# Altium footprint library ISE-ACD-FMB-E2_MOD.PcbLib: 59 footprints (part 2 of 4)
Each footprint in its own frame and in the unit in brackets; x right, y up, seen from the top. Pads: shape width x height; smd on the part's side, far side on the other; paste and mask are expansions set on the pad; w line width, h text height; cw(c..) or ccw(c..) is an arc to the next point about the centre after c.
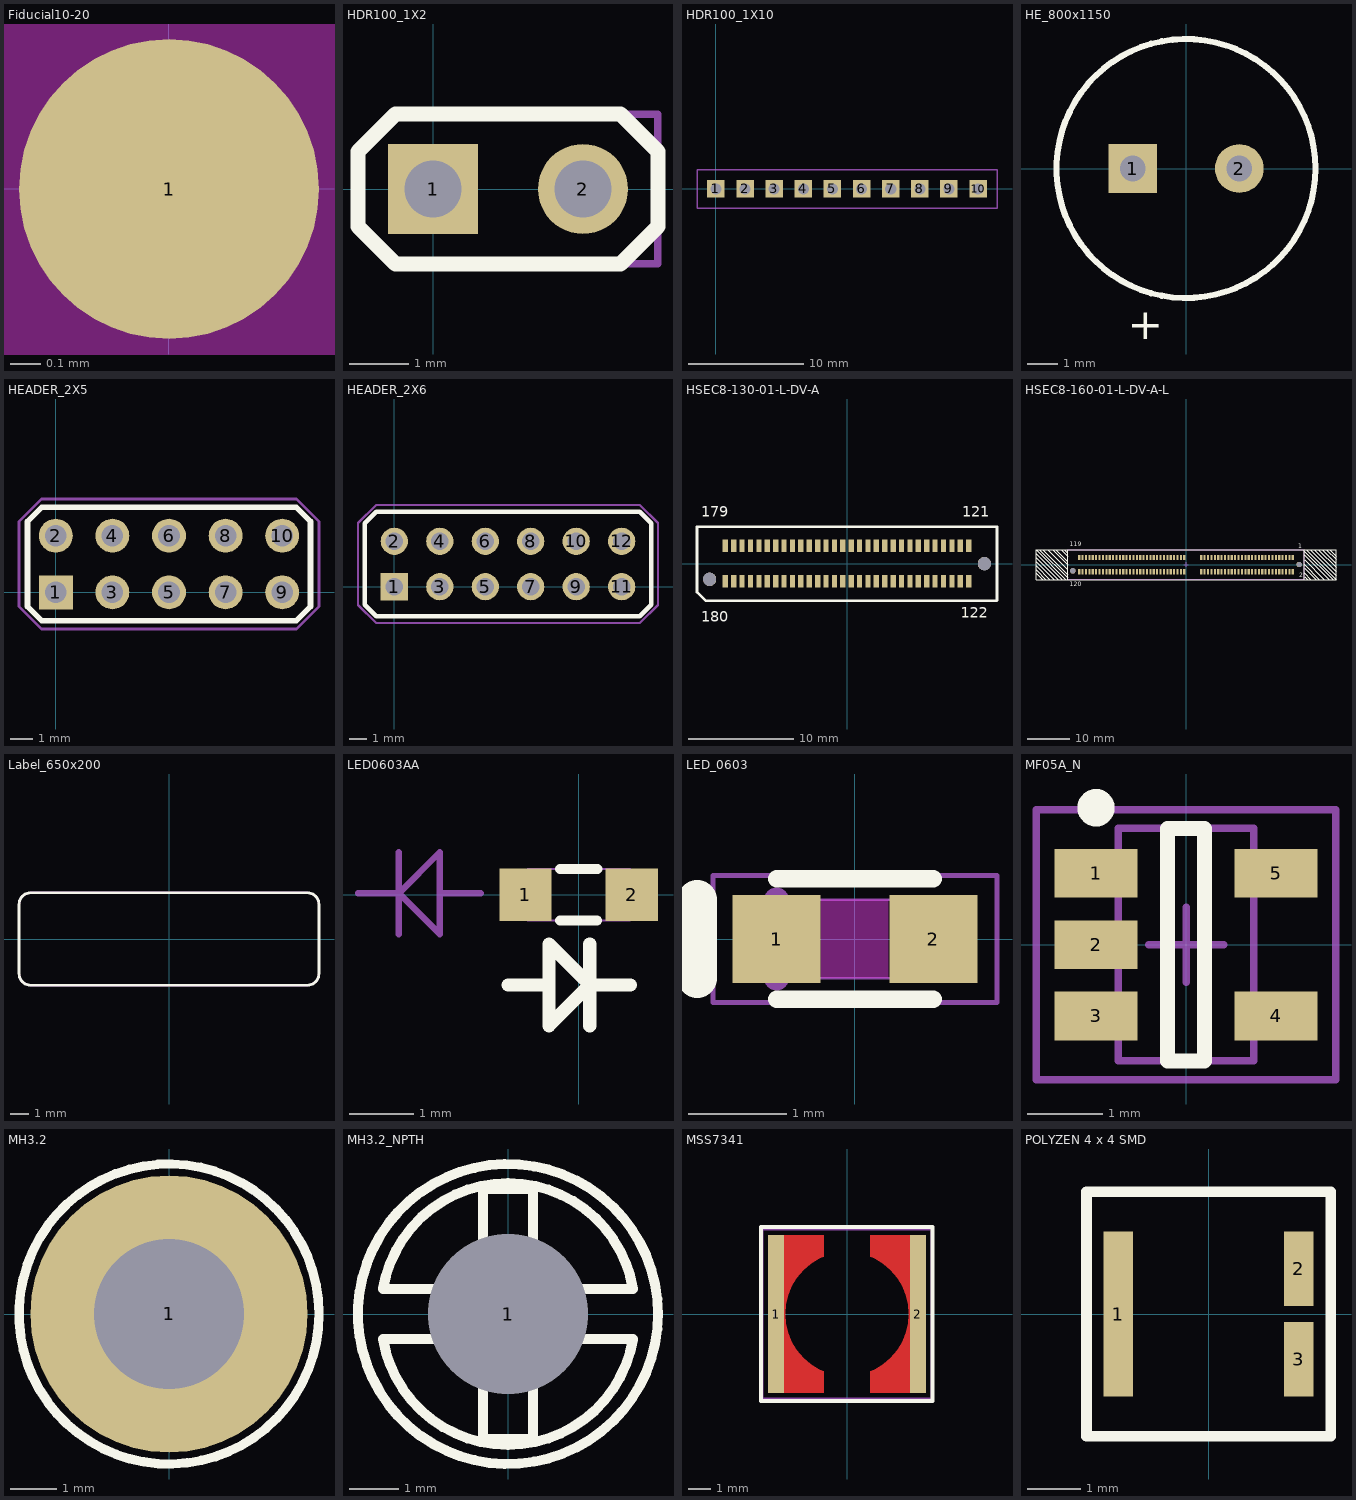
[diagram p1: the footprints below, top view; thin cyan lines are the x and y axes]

## Fiducial10-20 [mm]
pads (1):
  round 1 smd mask+0.5: 1(0,0)
Top Layer keep-out:
  circle w1.178: c0,0 r0.5

## HDR100_1X2 [mil]
pads (2):
  rect 60x60 hole 38: 1(0,0)
  round 60 hole 38: 2(100,0)
Top Overlay:
  lines w10: -50,-25 -50,25 -25,50 125,50 150,25 150,-25 125,-50 -25,-50 -50,-25
Mechanical 5:
  lines w5: -50,-25 -25,-50 150,-50 150,50 -25,50 -50,25 -50,-25
  text ".Designator" at 70,-46 h36

## HDR100_1X10 [mil]
pads (10):
  rect 60x60 hole 38: 1(0,0) 2(100,0) 3(200,0) 4(300,0) 5(400,0) 6(500,0) 7(600,0) 8(700,0) 9(800,0) 10(900,0)
Mechanical 5:
  lines w5: -65.1,-66 964.9,-66 964.9,65 -65.1,65 -65.1,-66
  text "*" at -47,16 h40
  text ".Designator" at 410,74 h36

## HE_800x1150 [mm] "NICHICON"
height 13
pads (2):
  rect 1.6x1.6 hole 0.838: 1(-1.75,0)
  round 1.6 hole 0.838: 2(1.75,0)
Top Overlay:
  circle w0.2: c0,0 r4.25
  text "+" at -1.905,-5.595 h1.02
Mechanical 5:
  circle w0.1: c0,0 r4.25
  text "+" at -5.2,-0.5 h1.02
  text ".Designator" at -0.457,1.295 h0.91
3D body: height 11.51, standoff -4, extent -4.217,-4.243 4.244,4.243

## HEADER_2X5 [mil]
pads (10):
  rect 60x60 hole 38: 1(0,0)
  round 60 hole 38: 2(0,100) 3(100,0) 4(100,100) 5(200,0) 6(200,100) 7(300,0) 8(300,100) 9(400,0) 10(400,100)
Top Overlay:
  lines w10: -50,-25 -25,-50 425,-50 450,-25 450,125 425,150 -25,150 -50,125 -50,-25
Mechanical 5:
  lines w5: -65,-25 -25,-65 425,-65 465,-25 465,125 425,165 -25,165 -65,125 -65,-25
  text "*" at -32,-47 h40
  text ".Designator" at 247,69 h36

## HEADER_2X6 [mil]
pads (12):
  rect 60x60 hole 38: 1(0,0)
  round 60 hole 38: 2(0,100) 3(100,0) 4(100,100) 5(200,0) 6(200,100) 7(300,0) 8(300,100) 9(400,0) 10(400,100) 11(500,0) 12(500,100)
Top Overlay:
  lines w10: -65,-40 -40,-65 540,-65 565,-40 565,140 540,165 -40,165 -65,140 -65,-40
Mechanical 5:
  lines w5: -80,-40 -40,-80 540,-80 580,-40 580,140 540,180 -40,180 -80,140 -80,-40
  text "*" at -46,-58 h40
  text ".Designator" at 268,4 h36

## HSEC8-130-01-L-DV-A [mm]
pads (62):
  rect 0.5x1.2 smd: 121(11.6,1.7) 122(11.6,-1.7) 123(10.8,1.7) 124(10.8,-1.7) 125(10,1.7) 126(10,-1.7) 127(9.2,1.7) 128(9.2,-1.7) 129(8.4,1.7) 130(8.4,-1.7) 131(7.6,1.7) 132(7.6,-1.7) 133(6.8,1.7) 134(6.8,-1.7) 135(6,1.7) 136(6,-1.7) 137(5.2,1.7) 138(5.2,-1.7) 139(4.4,1.7) 140(4.4,-1.7) 141(3.6,1.7) 142(3.6,-1.7) 143(2.8,1.7) 144(2.8,-1.7) 145(2,1.7) 146(2,-1.7) 147(1.2,1.7) 148(1.2,-1.7) 149(0.4,1.7) 150(0.4,-1.7) 151(-0.4,1.7) 152(-0.4,-1.7) 153(-1.2,1.7) 154(-1.2,-1.7) 155(-2,1.7) 156(-2,-1.7) 157(-2.8,1.7) 158(-2.8,-1.7) 159(-3.6,1.7) 160(-3.6,-1.7) 161(-4.4,1.7) 162(-4.4,-1.7) 163(-5.2,1.7) 164(-5.2,-1.7) 165(-6,1.7) 166(-6,-1.7) 167(-6.8,1.7) 168(-6.8,-1.7) 169(-7.6,1.7) 170(-7.6,-1.7) 171(-8.4,1.7) 172(-8.4,-1.7) 173(-9.2,1.7) 174(-9.2,-1.7) 175(-10,1.7) 176(-10,-1.7) 177(-10.8,1.7) 178(-10.8,-1.7) 179(-11.6,1.7) 180(-11.6,-1.7)
  round 1.27 hole 1.27 unplated mask+0.127: 181(13.1,0) 182(-13.1,-1.5)
Top Overlay:
  lines w0.254: 14.246,-3.554 -13.464,-3.554 -14.3,-2.718 -14.3,1.75 -14.3,3.5 14.3,3.5 14.3,-3.5
  text "180" at -13.898,-5.563 h1.02
  text "179" at -13.898,4.47 h1.02
  text "121" at 10.994,4.47 h1.02
  text "122" at 10.867,-5.182 h1.02
Mechanical 13:
  lines w0.1: -14.3,-2.7 -14.3,3.5 14.3,3.5 14.3,-3.5 -13.5,-3.5 -14.3,-2.7

## HSEC8-160-01-L-DV-A-L [mm] "CONN HIGH SPD CARD EDGE 120 POS"
height 12.4
pads (122):
  rect 0.5x1.2 smd: 1(25.2,1.7) 2(25.2,-1.7) 3(24.4,1.7) 4(24.4,-1.7) 5(23.6,1.7) 6(23.6,-1.7) 7(22.8,1.7) 8(22.8,-1.7) 9(22,1.7) 10(22,-1.7) 11(21.2,1.7) 12(21.2,-1.7) 13(20.4,1.7) 14(20.4,-1.7) 15(19.6,1.7) 16(19.6,-1.7) 17(18.8,1.7) 18(18.8,-1.7) 19(18,1.7) 20(18,-1.7) 21(17.2,1.7) 22(17.2,-1.7) 23(16.4,1.7) 24(16.4,-1.7) 25(15.6,1.7) 26(15.6,-1.7) 27(14.8,1.7) 28(14.8,-1.7) 29(14,1.7) 30(14,-1.7) 31(13.2,1.7) 32(13.2,-1.7) 33(12.4,1.7) 34(12.4,-1.7) 35(11.6,1.7) 36(11.6,-1.7) 37(10.8,1.7) 38(10.8,-1.7) 39(10,1.7) 40(10,-1.7) 41(9.2,1.7) 42(9.2,-1.7) 43(8.4,1.7) 44(8.4,-1.7) 45(7.6,1.7) 46(7.6,-1.7) 47(6.8,1.7) 48(6.8,-1.7) 49(6,1.7) 50(6,-1.7) 51(5.2,1.7) 52(5.2,-1.7) 53(4.4,1.7) 54(4.4,-1.7) 55(3.6,1.7) 56(3.6,-1.7) 57(-0.4,1.7) 58(-0.4,-1.7) 59(-1.2,1.7) 60(-1.2,-1.7) 61(-2,1.7) 62(-2,-1.7) 63(-2.8,1.7) 64(-2.8,-1.7) 65(-3.6,1.7) 66(-3.6,-1.7) 67(-4.4,1.7) 68(-4.4,-1.7) 69(-5.2,1.7) 70(-5.2,-1.7) 71(-6,1.7) 72(-6,-1.7) 73(-6.8,1.7) 74(-6.8,-1.7) 75(-7.6,1.7) 76(-7.6,-1.7) 77(-8.4,1.7) 78(-8.4,-1.7) 79(-9.2,1.7) 80(-9.2,-1.7) 81(-10,1.7) 82(-10,-1.7) 83(-10.8,1.7) 84(-10.8,-1.7) 85(-11.6,1.7) 86(-11.6,-1.7) 87(-12.4,1.7) 88(-12.4,-1.7) 89(-13.2,1.7) 90(-13.2,-1.7) 91(-14,1.7) 92(-14,-1.7) 93(-14.8,1.7) 94(-14.8,-1.7) 95(-15.6,1.7) 96(-15.6,-1.7) 97(-16.4,1.7) 98(-16.4,-1.7) 99(-17.2,1.7) 100(-17.2,-1.7) 101(-18,1.7) 102(-18,-1.7) 103(-18.8,1.7) 104(-18.8,-1.7) 105(-19.6,1.7) 106(-19.6,-1.7) 107(-20.4,1.7) 108(-20.4,-1.7) 109(-21.2,1.7) 110(-21.2,-1.7) 111(-22,1.7) 112(-22,-1.7) 113(-22.8,1.7) 114(-22.8,-1.7) 115(-23.6,1.7) 116(-23.6,-1.7) 117(-24.4,1.7) 118(-24.4,-1.7) 119(-25.2,1.7) 120(-25.2,-1.7)
  round 1.27 hole 1.27 unplated mask+0.127: 121(-26.7,-1.5) 122(26.7,0)
Top Overlay:
  lines w0.2: -35.4,-2.032 -33.909,-3.523 ; -35.4,-1.27 -33.114,-3.556 ; -35.4,0.635 -31.242,-3.523 ; -35.4,1.651 -30.226,-3.523 ; -35.4,2.54 -29.337,-3.523 ; -35.353,-0.334 -32.131,-3.556 ; -34.58,3.465 -27.94,-3.175 ; -33.782,3.5 -27.9,-2.382 ; -32.639,3.5 -27.996,-1.143 ; -31.496,3.5 -27.9,-0.096 ; -30.734,3.5 -27.996,0.762 ; -29.464,3.5 -27.9,1.936 ; -28.702,3.5 -27.996,2.794 ; -28.344,-3.556 -35.4,3.5 ; 27.9,-1.992 29.464,-3.556 ; 27.9,0.04 31.496,-3.556 ; 27.9,2.326 33.782,-3.556 ; 27.94,3.119 34.58,-3.52 ; 27.996,-2.85 28.702,-3.556 ; 27.996,-0.818 30.734,-3.556 ; 27.996,1.087 32.639,-3.556 ; 28.344,3.5 35.4,-3.556 ; 29.337,3.467 35.4,-2.596 ; 30.226,3.467 35.4,-1.707 ; 31.242,3.467 35.4,-0.691 ; 32.131,3.5 35.353,0.278 ; 33.114,3.5 35.4,1.214 ; 33.909,3.467 35.4,1.976 ; -35.4,3.5 -27.9,3.5 ; -35.4,3.5 -35.4,-3.556 -27.9,-3.556 ; -27.9,-3.556 -27.9,3.5 ; -27.9,-3.556 27.9,-3.556 ; -27.9,3.5 27.9,3.5 ; 27.9,-3.556 27.9,3.5 ; 27.9,-3.556 35.4,-3.556 ; 27.9,-3.556 27.9,3.5 ; 27.9,3.5 35.4,3.5 35.4,-3.556
  text "2" at 26.67,-3.048 h1.02
  text "1" at 26.543,3.81 h1.02
  text "119" at -27.432,4.318 h1.02
  text "120" at -27.432,-5.08 h1.02
Mechanical 13:
  lines w0.1: 27.9,-3.556 27.9,3.444 ; -27.9,-3.5 27.9,-3.5 27.9,3.5 -27.9,3.5 -27.9,-3.5
Mechanical 15:
  lines w0.1: -0.5,0 0.5,0 ; 0,-0.5 0,0.5

## Label_650x200 [mm] "Thermal Transfer Label"
height 0.025
Top Overlay:
  lines w0.152: -8.255,-1.905 ccw(c-7.62,-1.905) -7.62,-2.54 7.62,-2.54 ccw(c7.62,-1.905) 8.255,-1.905 8.255,1.905 ccw(c7.62,1.905) 7.62,2.54 -7.62,2.54 ccw(c-7.62,1.905) -8.255,1.905 -8.255,-1.905
Mechanical 5:
  lines w0.127: -8.255,-1.905 ccw(c-7.62,-1.905) -7.62,-2.54 7.62,-2.54 ccw(c7.62,-1.905) 8.255,-1.905 8.255,1.905 ccw(c7.62,1.905) 7.62,2.54 -7.62,2.54 ccw(c-7.62,1.905) -8.255,1.905 -8.255,-1.905
  text ".Designator" at -1.524,-0.508 h0.91
3D body: height 0.03, standoff 0, extent -8.268,-2.553 8.268,2.553

## LED0603AA [mil]
height 35.43
pads (2):
  rect 32x32 smd: 1(-32.48,0) 2(32.48,0)
Top Overlay:
  lines w6: -11.42,-15.75 11.42,-15.75 ; -11.42,15.75 11.42,15.75
  lines w8: -43.21,-55.04 -18.21,-55.04 ; 6.79,-80.04 6.79,-30.04 ; 31.79,-55.04 6.79,-55.04 ; 6.79,-55.04 -18.21,-30.04 -18.21,-80.04 6.79,-55.04
Mechanical 15:
  lines w1: -31.5,-15.75 -31.5,15.75 31.5,15.75 31.5,-15.75 -31.5,-15.75
  lines w3.94: -134.79,0.96 -109.79,0.96 ; -109.79,-24.04 -109.79,25.96 ; -84.79,0.96 -59.79,0.96 ; -109.79,0.96 -84.79,-24.04 -84.79,25.96 -109.79,0.96

## LED_0603 [mm] "LED, HIGHBRIGHT, BLUE, SMT0603"
height 0.8
pads (2):
  rect 0.9x0.9 smd paste+0: 1(-0.8,0) 2(0.8,0)
Top Layer keep-out:
  rectangle: -0.35,-0.4 0.344,0.402
Top Overlay:
  lines w0.178: -0.8,-0.616 0.8,-0.616 ; -0.8,0.616 0.8,0.616
  lines w0.405: -1.613,-0.4 -1.613,0.4
  text ".Designator" at -1.524,1 h1.02
Mechanical 5:
  lines w0.025: -0.8,-0.4 0.8,-0.4 0.8,0.4 -0.8,0.4
  lines w0.254: -0.8,-0.4 -0.8,0.4
  text ".Designator" at -1.524,-0.508 h1.02
Mechanical 15:
  lines w0.05: -1.45,-0.65 1.45,-0.65 1.45,0.65 -1.45,0.65 -1.45,-0.65
3D body: height 0.8, standoff 0, extent -0.8,-0.4 0.8,0.4

## MF05A_N [mm] "SOT23, 5-Leads, Body 2.9x1.6mm, Pitch 0.95mm, Lead Span 2.8mm, IPC Medium Density"
height 1.19
pads (5):
  rect 1.1x0.65 smd: 1(-1.2,0.95) 2(-1.2,0) 3(-1.2,-0.95) 4(1.2,-0.95) 5(1.2,0.95)
Top Overlay:
  circle w0.25: c-1.2,1.825 r0.125
  lines w0.2: -0.25,-1.55 -0.25,1.55 0.25,1.55 0.25,-1.55 -0.25,-1.55
Mechanical 5:
  text ".Designator" at 0.457,-0.737 h0.91
Mechanical 13:
  lines w0.1: -0.9,-1.55 0.9,-1.55 0.9,1.55 -0.9,1.55 -0.9,-1.55
Mechanical 15:
  lines w0.1: -0.5,0 0.5,0 ; 0,-0.5 0,0.5 ; -2,-1.8 2,-1.8 2,1.8 -2,1.8 -2,-1.8
3D body: height 1.19, standoff 0, extent -0.9,-1.55 0.9,1.55

## MH3.2 [mm]
height 2.032
pads (1):
  round 6 / inner round 3.607 / far side round 6 hole 3.251: 1(0,0)
Top Overlay:
  lines w0.203: 3.25,0 cw(c0,0) 3.25,0.014

## MH3.2_NPTH [mil]
pads (1):
  round 20 / inner round 142 / far side round 20 hole 128 unplated mask+65: 1(0,0)
Top Overlay:
  circle w8: c0,0 r120
  lines w8: -100,-20 -20,-20 -20,-100 20,-100 20,-20 100,-20 ; -100.02,-19.91 ccw(c0,-3.35) 99.99,-20.08 ; -100,20 -20,20 -20,100 20,100 20,20 100,20 ; -99.99,20.09 cw(c0,3.36) 100.02,19.92

## MSS7341 [mm] "Coilcraft recommended land pattern Document 383-2 1/3/11"
height 4.1
pads (2):
  rect 0.725x7.112 smd: 1(-3.187,0) 2(3.187,0)
Top Layer:
  region: 1.05,-3.55 1.05,-2.57 1.05,-2.569 1.264,-2.48 1.636,-2.252 1.968,-1.968 2.252,-1.636 2.48,-1.264 2.647,-0.86 2.749,-0.435 2.784,0 2.749,0.435 2.647,0.86 2.48,1.264 2.252,1.636 1.968,1.968 1.636,2.252 1.264,2.48 1.057,2.566 1.05,2.566 1.05,3.55 3.55,3.55 3.55,-3.55
  region: -1.05,-3.55 -1.05,-2.57 -1.05,-2.569 -1.264,-2.48 -1.636,-2.252 -1.968,-1.968 -2.252,-1.636 -2.48,-1.264 -2.647,-0.86 -2.749,-0.435 -2.784,0 -2.749,0.435 -2.647,0.86 -2.48,1.264 -2.252,1.636 -1.968,1.968 -1.636,2.252 -1.264,2.48 -1.057,2.566 -1.05,2.566 -1.05,3.55 -3.55,3.55 -3.55,-3.55
Top Overlay:
  lines w0.178: -3.861,-1.397 -3.861,1.372 -3.861,3.912 -3.556,3.912 2.286,3.912 ; -3.861,-1.372 -3.861,-3.912 -2.921,-3.912 ; -2.896,-3.912 2.946,-3.912 3.835,-3.912 3.835,-1.143 ; 2.311,3.912 3.835,3.912 3.835,-1.168
Top Paste:
  region: -1.05,-3.55 -1.05,-2.57 -1.05,-2.569 -1.264,-2.48 -1.636,-2.252 -1.968,-1.968 -2.252,-1.636 -2.48,-1.264 -2.647,-0.86 -2.749,-0.435 -2.784,0 -2.749,0.435 -2.647,0.86 -2.48,1.264 -2.252,1.636 -1.968,1.968 -1.636,2.252 -1.264,2.48 -1.057,2.566 -1.05,2.566 -1.05,3.55 -3.55,3.55 -3.55,-3.55
  region: 1.05,-3.55 1.05,-2.57 1.05,-2.569 1.264,-2.48 1.636,-2.252 1.968,-1.968 2.252,-1.636 2.48,-1.264 2.647,-0.86 2.749,-0.435 2.784,0 2.749,0.435 2.647,0.86 2.48,1.264 2.252,1.636 1.968,1.968 1.636,2.252 1.264,2.48 1.057,2.566 1.05,2.566 1.05,3.55 3.55,3.55 3.55,-3.55
Top Solder:
  region: 0.999,-3.601 0.999,-2.586 1,-2.589 1.264,-2.48 1.636,-2.252 1.968,-1.968 2.252,-1.636 2.48,-1.264 2.647,-0.86 2.749,-0.435 2.784,0 2.749,0.435 2.647,0.86 2.48,1.264 2.252,1.636 1.968,1.968 1.636,2.252 1.264,2.48 1.007,2.586 0.999,2.566 0.999,3.601 3.601,3.606 3.607,-3.601
  region: -0.999,-3.601 -0.999,-2.586 -1,-2.589 -1.264,-2.48 -1.636,-2.252 -1.968,-1.968 -2.252,-1.636 -2.48,-1.264 -2.647,-0.86 -2.749,-0.435 -2.784,0 -2.749,0.435 -2.647,0.86 -2.48,1.264 -2.252,1.636 -1.968,1.968 -1.636,2.252 -1.264,2.48 -1.007,2.586 -0.999,2.566 -0.999,3.601 -3.601,3.606 -3.607,-3.601
Mechanical 5:
  lines w0.102: -3.81,-3.81 3.81,-3.81 3.81,3.81 -3.81,3.81 -3.81,-3.81
  text ".Designator" at 0.495,-0.711 h0.91
3D body: height 4.12, standoff 0.02, extent -3.78,-3.78 3.78,3.78

## POLYZEN 4 x 4 SMD [mm] "POLYZEN 4 x 4 SMD"
height 2
pads (3):
  rect 0.56x3.1 smd: 1(-1.7,0)
  rect 0.56x1.4 smd: 2(1.7,0.85) 3(1.7,-0.85)
Top Overlay:
  lines w0.2: -2.3,-2.3 2.3,-2.3 2.3,2.3 -2.3,2.3 -2.3,-2.3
